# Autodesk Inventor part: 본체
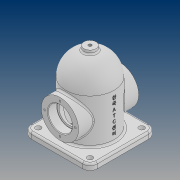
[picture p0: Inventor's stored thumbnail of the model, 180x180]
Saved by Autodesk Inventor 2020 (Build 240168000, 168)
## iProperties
Created: 2021-08
Part Number: 본체
Material: 일반
Document SubType Name: Modeling
Designer: PC312-
Density: 1 g/cm^3
Appearance: 기본값
Mass: 320.701 g
Surface Area: 801.07 cm^2
Volume: 320.701 cm^3
Author: PC312-
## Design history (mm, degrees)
sketch "스케치1"
  geometry: L1 (0, 0)-(114, 0); L2 (0, 0)-(0, -40); L3 (0, -40)-(74, -40); L4 (114, 0)-(114, 0); L5 (74, -32)-(0, -32); L6 (106, 0)-(106, 0); A1 r 40 centre (74, 0) between (74, -40) and (114, 0); A2 r 32 centre (74, 0) between (74, -32) and (106, 0); 2 further points
  constraints: 12 end point, 4 point on circle, 4 tangent, 2 centre point, 2 horizontal, 2 point on line, 2 vertical
  dimensions: "d0" = 114 distance of L1.start L1.end; "d1" = 80 diameter of L3 L1; "d35" = 8 distance between parallel lines of L3 L5; "d37" = 40 radius of A1; "d38" = 32 radius of A2
node "작업 평면1"
revolve "회전3" stored, may be unused: angle "d39" = 90 deg
sketch "스케치6"
  geometry: L1 (-55, 55)-(55, 55); L2 (55, 55)-(55, -55); L3 (55, -55)-(-55, -55); L4 (-55, -55)-(-55, 55); L5 (-55, 55)-(55, -55); L6 (55, 55)-(-55, -55); C1 r 32 at (0, 0) reference; 1 further point
  constraints: 12 end point, 2 midpoint, 2 parallel, 1 horizontal, 1 perpendicular
  dimensions: "d40" = 110 distance of L2.end L3.end; "d41" = 110 distance of L1.end L2.end
extrude "돌출2" join sketch "스케치6" distance "d42" = 10; taper "d43" = 0 deg
node "작업 평면2"
sketch "스케치7"
  geometry: L1 (55, 0)-(-55, 0) reference; L2 (55, -10)-(-55, -10) reference; C1 r 31 at (0, 38); 2 further points
  constraints: 1 centre point, 1 midpoint, 1 vertical alignment
  dimensions: "d45" = 62 diameter of C1; "d46" = 48 distance from line of L2 C1.centre
extrude "돌출3" join sketch "스케치7" stored distance "d47" = 10; taper "d48" = 0 deg
sketch "스케치8"
  geometry: C1 r 31 at (0, 0) reference; 2 further points
  constraints: 1 coincident
hole "구멍4" sketch "스케치8" at (0, 0) diameter "d49" = 40; stored, may be unused: countersink angle "d53" = 90 deg, drill point angle "d55" = 0 deg; dims "d50" = 8, "d51" = 14, "d52" = 16, "d54" = 15
sketch "스케치9"
  geometry: C1 r 31 at (0, 0) reference; 2 further points
  constraints: 1 vertical alignment
  dimensions: "d56" = 25.5 distance of point (0, 25.5) C1.centre
hole "구멍5" sketch "스케치9" at (0, 25.5) diameter "d57" = 3.242; stored, may be unused: countersink angle "d61" = 90 deg, drill point angle "d63" = 118 deg; dims "d58" = 8, "d59" = 14, "d60" = 16, "d62" = 10
sketch "스케치10"
  geometry: C1 r 20 at (0, 0) reference; 2 further points
  constraints: 1 coincident
hole "구멍6" sketch "스케치10" at (0, 0) diameter "d67" = 33; stored, may be unused: countersink angle "d71" = 90 deg, drill point angle "d73" = 118 deg; dims "d68" = 8, "d69" = 14, "d70" = 16, "d72" = 10
fillet "모깎기2" dims "d74" = 12
sketch "스케치11"
  geometry: A1 r 12 centre (43, -43) between (43, -55) and (55, -43) reference; A2 r 12 centre (-43, -43) between (-55, -43) and (-43, -55) reference; A3 r 12 centre (-43, 43) between (-43, 55) and (-55, 43) reference; A4 r 12 centre (43, 43) between (55, 43) and (43, 55) reference; 1 further point
hole "구멍7" sketch "스케치11" at (43, 43), (-43, 43), (-43, -43), (43, -43) diameter "d75" = 9; stored, may be unused: countersink angle "d79" = 90 deg, drill point angle "d81" = 118 deg; dims "d76" = 8, "d77" = 14, "d78" = 16, "d80" = 10
fillet "모깎기3" dims "d82" = 3
node "작업 평면3"
sketch "스케치12"
  geometry: C1 r 10 at (0, 0); 1 further point
  constraints: 1 centre point, 1 coincident
  dimensions: "d84" = 20 diameter of C1
extrude "돌출4" join sketch "스케치12" stored distance "d85" = 10; taper "d86" = 0 deg
sketch "스케치13"
  geometry: C1 r 10 at (0, 0) reference; 2 further points
  constraints: 1 coincident
hole "구멍8" sketch "스케치13" at (0, 0) diameter "d87" = 5.1881; stored, may be unused: countersink angle "d91" = 90 deg, drill point angle "d93" = 118 deg; dims "d88" = 12, "d89" = 14, "d90" = 16, "d92" = 16
fillet "모깎기4" dims "d94" = 3
chamfer "모따기1" distance "d95" = 1; stored, may be unused: second distance "d96" = 2, angle "d97" = 45 deg
node "작업 평면4"
sketch "스케치14"
  geometry: L1 (-10, -43)-(-10, 43) reference; 2 further points
  constraints: 1 horizontal alignment, 1 other
  dimensions: "d99" = 48 distance from line of point (38, 0) L1
feature "엠보싱1" sketch "스케치14" dims "d0" = 114, "d1" = 80, "d35" = 8, "d37" = 40, "d38" = 32, "d100" = 0.5, "d101" = 0
fillet "모깎기5" dims "d102" = 0.3
node "솔리드3"
pattern_circular "원형 패턴2" dims angle "d65" = 360 deg
mirror "미러2"
feature "A9D066F2-1C7D-4E18-AEED-F7BC21143FA4" dims "d49" = 40, "d50" = 8, "d51" = 14, "d52" = 16, "d53" = 90 deg, "d54" = 15, "d55" = 0
other parameters: "d83" = -129, "d98" = 75
